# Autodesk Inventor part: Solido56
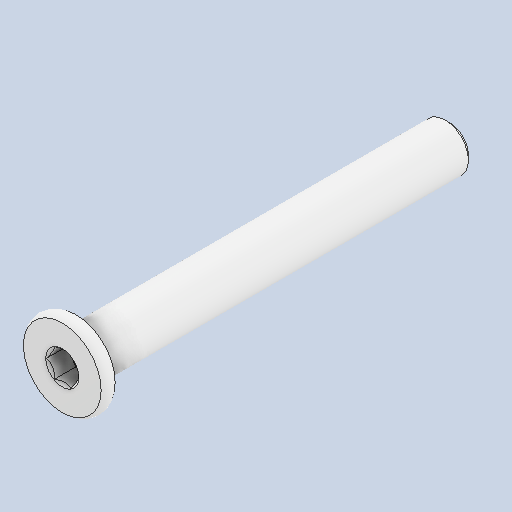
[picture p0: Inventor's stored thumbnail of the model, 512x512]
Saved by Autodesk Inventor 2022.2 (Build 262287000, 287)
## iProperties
Created: 2024-10
Part Number: Solido56
Material: Generico
Document SubType Name: Modeling
Designer: 18907419
Density: 1 g/cm^3
Appearance: Default
Author: 18907419
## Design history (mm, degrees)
feature "Solido56"
node "Solido1"
